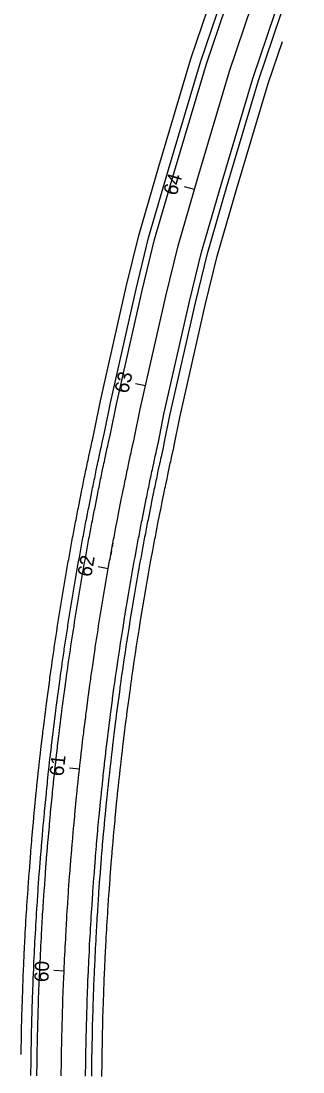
# Model space of a CAD drawing. Extents: x 2318076 to 2324211, y 613525 to 629939.
# Drawn here: x 2318594 to 2318733, y 620852 to 621371 of the extents above; entities that cross this region are included whole.
import ezdxf

# ---------------------------------------------------------------- set-up
doc = ezdxf.new("R2010")
doc.units = 0
for name, color, linetype in [('GE_P_CL_50', 7, 'Continuous'), ('PV_P_EOP', 7, 'Continuous'), ('PV_P_Shoulder', 7, 'Continuous'), ('RD_X_GR_Lt', 7, 'Continuous'), ('RD_X_GR_Rt', 7, 'Continuous')]:
    doc.layers.add(name, color=color, linetype=linetype)

msp = doc.modelspace()

# ---------------------------------------------------------------- linework, layer by layer
at = {"layer": 'GE_P_CL_50'}
for p, q in [((2318679.71, 621288.18), (2318674.91, 621289.57)), ((2318655.58, 621191.17), (2318650.7, 621192.27)), ((2318637.23, 621100.93), (2318632.3, 621101.8)), ((2318623.06, 621001.95), (2318618.09, 621002.5)), ((2318615.45, 620902.26), (2318610.45, 620902.47))]:
    msp.add_line(p, q, dxfattribs=at)
msp.add_lwpolyline([(2318614.1, 620850.47), (2318614.18, 620857.38), (2318614.19, 620858.37), (2318614.43, 620871.21), (2318614.45, 620872.19), (2318614.52, 620875.16), (2318614.55, 620876.14), (2318614.63, 620879.11), (2318614.65, 620880.09), (2318614.74, 620883.06), (2318614.77, 620884.04), (2318614.87, 620887), (2318614.9, 620887.99), (2318615.04, 620891.94), (2318615.07, 620892.93), (2318615.15, 620894.9), (2318615.19, 620895.89), (2318615.22, 620896.87), (2318615.26, 620897.86), (2318615.47, 620902.8), (2318615.51, 620903.78), (2318615.56, 620904.77), (2318615.6, 620905.76), (2318615.74, 620908.72), (2318615.79, 620909.7), (2318615.93, 620912.66), (2318615.98, 620913.65), (2318616.03, 620914.64), (2318616.08, 620915.62), (2318616.24, 620918.58), (2318616.29, 620919.57), (2318616.46, 620922.53), (2318616.51, 620923.51), (2318616.57, 620924.5), (2318616.63, 620925.48), (2318616.8, 620928.44), (2318616.86, 620929.43), (2318617.05, 620932.39), (2318617.11, 620933.37), (2318617.64, 620941.26), (2318617.7, 620942.24), (2318618.2, 620949.14), (2318618.27, 620950.12), (2318618.96, 620958.99), (2318619.04, 620959.97), (2318619.45, 620964.89), (2318619.54, 620965.88), (2318620.14, 620972.76), (2318620.23, 620973.75), (2318620.68, 620978.66), (2318620.78, 620979.65), (2318621.64, 620988.5), (2318621.74, 620989.48), (2318622.14, 620993.41), (2318622.25, 620994.39), (2318622.77, 620999.3), (2318622.87, 621000.28), (2318623.41, 621005.19), (2318623.52, 621006.17), (2318624.08, 621011.08), (2318624.2, 621012.06), (2318624.78, 621016.97), (2318624.9, 621017.95), (2318625.13, 621019.91), (2318625.25, 621020.89), (2318626.11, 621027.75), (2318626.23, 621028.73), (2318626.48, 621030.69), (2318626.61, 621031.67), (2318627.39, 621037.54), (2318627.52, 621038.52), (2318628.18, 621043.42), (2318628.32, 621044.4), (2318628.59, 621046.35), (2318628.73, 621047.33), (2318629, 621049.29), (2318629.14, 621050.26), (2318629.42, 621052.22), (2318629.56, 621053.2), (2318630.27, 621058.08), (2318630.42, 621059.06), (2318630.71, 621061.02), (2318630.86, 621061.99), (2318631.45, 621065.9), (2318631.6, 621066.87), (2318632.05, 621069.8), (2318632.2, 621070.78), (2318632.51, 621072.73), (2318632.66, 621073.71), (2318633.44, 621078.58), (2318633.6, 621079.56), (2318634.4, 621084.43), (2318634.56, 621085.41), (2318635.38, 621090.28), (2318635.55, 621091.25), (2318636.38, 621096.12), (2318636.55, 621097.09), (2318636.72, 621098.06), (2318636.89, 621099.04), (2318637.24, 621100.98), (2318637.41, 621101.95), (2318637.76, 621103.9), (2318637.93, 621104.87), (2318638.11, 621105.84), (2318638.28, 621106.81), (2318638.64, 621108.76), (2318638.81, 621109.73), (2318638.64, 621108.76), (2318638.46, 621107.79), (2318638.99, 621110.7), (2318639.17, 621111.67), (2318639.35, 621112.64), (2318639.53, 621113.61), (2318639.35, 621112.64), (2318639.17, 621111.67), (2318639.53, 621113.61), (2318639.71, 621114.59), (2318639.89, 621115.56), (2318640.08, 621116.53), (2318640.26, 621117.5), (2318640.44, 621118.47), (2318640.63, 621119.44), (2318640.81, 621120.41), (2318641, 621121.38), (2318641.18, 621122.35), (2318641.74, 621125.26), (2318641.93, 621126.23), (2318642.12, 621127.2), (2318642.31, 621128.17), (2318643.66, 621134.95), (2318643.85, 621135.92), (2318644.24, 621137.85), (2318644.44, 621138.82), (2318645.03, 621141.72), (2318645.23, 621142.69), (2318645.43, 621143.66), (2318645.63, 621144.63), (2318645.83, 621145.59), (2318646.03, 621146.56), (2318646.64, 621149.46), (2318646.85, 621150.43), (2318647.05, 621151.39), (2318647.26, 621152.36), (2318648.29, 621157.19), (2318648.5, 621158.15), (2318648.71, 621159.12), (2318648.92, 621160.08), (2318649.99, 621164.91), (2318650.2, 621165.87), (2318652.99, 621179.7), (2318665.59, 621235.58), (2318671.65, 621260.37), (2318681.36, 621293.88), (2318697.08, 621346.57), (2318719.13, 621411.93)], dxfattribs=at)
at = {"layer": 'PV_P_EOP'}
for points in [[(2318602.1, 620850.59), (2318602.18, 620857.53), (2318602.19, 620858.56), (2318602.43, 620871.45), (2318602.45, 620872.48), (2318602.52, 620875.46), (2318602.55, 620876.46), (2318602.63, 620879.44), (2318602.66, 620880.44), (2318602.75, 620883.42), (2318602.78, 620884.42), (2318602.87, 620887.4), (2318602.91, 620888.4), (2318603.04, 620892.37), (2318603.08, 620893.37), (2318603.16, 620895.36), (2318603.19, 620896.36), (2318603.23, 620897.35), (2318603.27, 620898.35), (2318603.48, 620903.31), (2318603.53, 620904.31), (2318603.57, 620905.31), (2318603.62, 620906.31), (2318603.75, 620909.28), (2318603.8, 620910.28), (2318603.95, 620913.26), (2318604, 620914.26), (2318604.05, 620915.25), (2318604.1, 620916.25), (2318604.26, 620919.22), (2318604.31, 620920.23), (2318604.48, 620923.2), (2318604.53, 620924.2), (2318604.59, 620925.19), (2318604.65, 620926.19), (2318604.83, 620929.16), (2318604.89, 620930.16), (2318605.07, 620933.14), (2318605.14, 620934.15), (2318605.66, 620942.07), (2318605.73, 620943.09), (2318606.23, 620950.01), (2318606.31, 620951.03), (2318607, 620959.94), (2318607.08, 620960.95), (2318607.5, 620965.9), (2318607.58, 620966.91), (2318608.19, 620973.83), (2318608.28, 620974.84), (2318608.74, 620979.78), (2318608.83, 620980.79), (2318609.7, 620989.68), (2318609.8, 620990.69), (2318610.21, 620994.64), (2318610.31, 620995.65), (2318610.84, 621000.58), (2318610.94, 621001.59), (2318611.49, 621006.52), (2318611.6, 621007.52), (2318612.16, 621012.45), (2318612.28, 621013.46), (2318612.86, 621018.39), (2318612.98, 621019.38), (2318613.22, 621021.36), (2318613.34, 621022.36), (2318614.2, 621029.25), (2318614.33, 621030.25), (2318614.58, 621032.22), (2318614.71, 621033.22), (2318615.49, 621039.12), (2318615.62, 621040.13), (2318616.29, 621045.05), (2318616.43, 621046.04), (2318616.7, 621048.01), (2318616.84, 621049), (2318617.12, 621050.97), (2318617.26, 621051.96), (2318617.54, 621053.92), (2318617.68, 621054.92), (2318618.4, 621059.83), (2318618.55, 621060.82), (2318618.84, 621062.79), (2318618.99, 621063.78), (2318619.59, 621067.71), (2318619.74, 621068.7), (2318620.19, 621071.64), (2318620.35, 621072.63), (2318620.66, 621074.6), (2318620.81, 621075.59), (2318621.6, 621080.49), (2318621.76, 621081.49), (2318622.56, 621086.38), (2318622.73, 621087.38), (2318623.55, 621092.28), (2318623.72, 621093.27), (2318624.56, 621098.16), (2318624.73, 621099.15), (2318624.9, 621100.13), (2318625.08, 621101.11), (2318625.42, 621103.07), (2318625.6, 621104.06), (2318625.95, 621106.01), (2318626.12, 621106.99), (2318626.3, 621107.97), (2318626.48, 621108.96), (2318626.83, 621110.91), (2318627.19, 621112.87), (2318627.37, 621113.85), (2318627.55, 621114.83), (2318627.73, 621115.81), (2318627.92, 621116.79), (2318628.1, 621117.76), (2318628.28, 621118.74), (2318628.47, 621119.72), (2318628.65, 621120.7), (2318628.84, 621121.68), (2318629.02, 621122.66), (2318629.21, 621123.63), (2318629.4, 621124.62), (2318629.96, 621127.54), (2318630.15, 621128.52), (2318630.34, 621129.5), (2318630.54, 621130.49), (2318631.89, 621137.3), (2318632.09, 621138.29), (2318632.48, 621140.24), (2318632.68, 621141.22), (2318633.28, 621144.14), (2318633.48, 621145.12), (2318633.68, 621146.09), (2318633.88, 621147.07), (2318634.08, 621148.04), (2318634.29, 621149.02), (2318634.9, 621151.93), (2318635.11, 621152.91), (2318635.31, 621153.89), (2318635.52, 621154.87), (2318636.56, 621159.72), (2318636.78, 621160.7), (2318636.99, 621161.67), (2318637.2, 621162.65), (2318638.27, 621167.5), (2318638.46, 621168.36), (2318641.25, 621182.21), (2318653.91, 621238.32), (2318660.05, 621263.47), (2318669.85, 621297.27), (2318685.64, 621350.2), (2318707.83, 621415.98)], [(2318650.44, 621106.61), (2318651.33, 621111.42), (2318651.51, 621112.38), (2318651.69, 621113.35), (2318651.87, 621114.31), (2318652.05, 621115.27), (2318652.23, 621116.24), (2318652.41, 621117.2), (2318652.6, 621118.16), (2318652.78, 621119.12), (2318652.97, 621120.08), (2318653.52, 621122.98), (2318653.71, 621123.94), (2318653.9, 621124.9), (2318654.08, 621125.85), (2318655.42, 621132.6), (2318655.61, 621133.55), (2318656, 621135.47), (2318656.2, 621136.42), (2318656.79, 621139.31), (2318656.98, 621140.27), (2318657.18, 621141.23), (2318657.38, 621142.19), (2318657.58, 621143.15), (2318657.78, 621144.1), (2318658.39, 621146.99), (2318658.59, 621147.94), (2318658.79, 621148.9), (2318658.99, 621149.85), (2318660.02, 621154.66), (2318660.23, 621155.61), (2318660.44, 621156.56), (2318660.65, 621157.51), (2318661.7, 621162.31), (2318661.94, 621163.38), (2318664.73, 621177.19), (2318677.27, 621232.84), (2318683.25, 621257.27), (2318692.87, 621290.49), (2318708.52, 621342.94), (2318730.43, 621407.88)], [(2318626.1, 620850.35), (2318626.18, 620857.23), (2318626.19, 620858.18), (2318626.42, 620870.96), (2318626.45, 620871.91), (2318626.52, 620874.86), (2318626.54, 620875.83), (2318626.62, 620878.78), (2318626.65, 620879.75), (2318626.74, 620882.69), (2318626.77, 620883.67), (2318626.86, 620886.61), (2318626.89, 620887.58), (2318627.03, 620891.51), (2318627.07, 620892.48), (2318627.14, 620894.44), (2318627.18, 620895.42), (2318627.22, 620896.4), (2318627.25, 620897.37), (2318627.46, 620902.28), (2318627.5, 620903.25), (2318627.55, 620904.23), (2318627.59, 620905.21), (2318627.73, 620908.15), (2318627.77, 620909.12), (2318627.92, 620912.07), (2318627.97, 620913.04), (2318628.02, 620914.02), (2318628.07, 620914.99), (2318628.22, 620917.94), (2318628.28, 620918.91), (2318628.44, 620921.85), (2318628.49, 620922.83), (2318628.55, 620923.8), (2318628.61, 620924.78), (2318628.78, 620927.72), (2318628.84, 620928.69), (2318629.03, 620931.63), (2318629.09, 620932.59), (2318629.61, 620940.44), (2318629.67, 620941.39), (2318630.17, 620948.26), (2318630.24, 620949.21), (2318630.93, 620958.03), (2318631, 620958.99), (2318631.41, 620963.88), (2318631.49, 620964.84), (2318632.09, 620971.7), (2318632.18, 620972.65), (2318632.63, 620977.55), (2318632.72, 620978.5), (2318633.58, 620987.31), (2318633.68, 620988.26), (2318634.08, 620992.17), (2318634.18, 620993.14), (2318634.7, 620998.02), (2318634.8, 620998.98), (2318635.34, 621003.87), (2318635.45, 621004.83), (2318636.01, 621009.71), (2318636.12, 621010.67), (2318636.69, 621015.55), (2318636.81, 621016.51), (2318637.05, 621018.46), (2318637.16, 621019.42), (2318638.01, 621026.25), (2318638.14, 621027.21), (2318638.39, 621029.16), (2318638.51, 621030.12), (2318639.28, 621035.96), (2318639.41, 621036.92), (2318640.07, 621041.79), (2318640.2, 621042.75), (2318640.47, 621044.69), (2318640.61, 621045.66), (2318640.88, 621047.61), (2318641.02, 621048.57), (2318641.3, 621050.52), (2318641.44, 621051.48), (2318642.15, 621056.34), (2318642.29, 621057.3), (2318642.58, 621059.24), (2318642.72, 621060.2), (2318643.31, 621064.09), (2318643.46, 621065.05), (2318643.91, 621067.96), (2318644.06, 621068.92), (2318644.36, 621070.86), (2318644.52, 621071.82), (2318645.29, 621076.67), (2318645.45, 621077.63), (2318646.24, 621082.48), (2318646.4, 621083.43), (2318647.21, 621088.28), (2318647.38, 621089.23), (2318648.21, 621094.07), (2318648.38, 621095.03), (2318648.54, 621095.99), (2318648.71, 621096.96), (2318649.05, 621098.89), (2318649.23, 621099.85), (2318649.57, 621101.78), (2318649.74, 621102.75), (2318649.92, 621103.71), (2318650.09, 621104.67), (2318650.44, 621106.61)]]:
    msp.add_lwpolyline(points, dxfattribs=at)
at = {"layer": 'PV_P_Shoulder'}
for points in [[(2318599.1, 620850.62), (2318599.18, 620857.57), (2318599.19, 620858.61), (2318599.43, 620871.52), (2318599.45, 620872.55), (2318599.53, 620875.53), (2318599.55, 620876.54), (2318599.63, 620879.52), (2318599.66, 620880.53), (2318599.75, 620883.51), (2318599.78, 620884.51), (2318599.87, 620887.5), (2318599.91, 620888.5), (2318600.05, 620892.48), (2318600.08, 620893.48), (2318600.16, 620895.47), (2318600.2, 620896.47), (2318600.24, 620897.47), (2318600.28, 620898.48), (2318600.48, 620903.44), (2318600.53, 620904.45), (2318600.57, 620905.44), (2318600.62, 620906.44), (2318600.76, 620909.42), (2318600.8, 620910.43), (2318600.95, 620913.41), (2318601, 620914.41), (2318601.05, 620915.41), (2318601.1, 620916.41), (2318601.26, 620919.38), (2318601.32, 620920.39), (2318601.48, 620923.37), (2318601.54, 620924.37), (2318601.6, 620925.37), (2318601.65, 620926.37), (2318601.83, 620929.34), (2318601.89, 620930.35), (2318602.08, 620933.33), (2318602.14, 620934.34), (2318602.67, 620942.27), (2318602.74, 620943.3), (2318603.24, 620950.23), (2318603.32, 620951.26), (2318604.01, 620960.17), (2318604.09, 620961.2), (2318604.51, 620966.15), (2318604.59, 620967.17), (2318605.2, 620974.09), (2318605.29, 620975.11), (2318605.75, 620980.06), (2318605.85, 620981.08), (2318606.71, 620989.98), (2318606.82, 620991), (2318607.22, 620994.95), (2318607.33, 620995.96), (2318607.85, 621000.9), (2318607.96, 621001.91), (2318608.51, 621006.85), (2318608.62, 621007.86), (2318609.18, 621012.8), (2318609.3, 621013.81), (2318609.88, 621018.74), (2318610, 621019.74), (2318610.24, 621021.72), (2318610.37, 621022.73), (2318611.23, 621029.63), (2318611.35, 621030.63), (2318611.61, 621032.61), (2318611.74, 621033.61), (2318612.52, 621039.52), (2318612.65, 621040.53), (2318613.32, 621045.45), (2318613.46, 621046.45), (2318613.73, 621048.42), (2318613.87, 621049.42), (2318614.15, 621051.39), (2318614.29, 621052.38), (2318614.57, 621054.35), (2318614.72, 621055.35), (2318615.43, 621060.27), (2318615.58, 621061.26), (2318615.87, 621063.23), (2318616.02, 621064.23), (2318616.62, 621068.16), (2318616.77, 621069.16), (2318617.23, 621072.1), (2318617.38, 621073.1), (2318617.69, 621075.06), (2318617.85, 621076.06), (2318618.63, 621080.97), (2318618.8, 621081.97), (2318619.6, 621086.87), (2318619.77, 621087.88), (2318620.59, 621092.78), (2318620.76, 621093.78), (2318621.6, 621098.67), (2318621.78, 621099.67), (2318621.95, 621100.65), (2318622.12, 621101.63), (2318622.47, 621103.59), (2318622.64, 621104.58), (2318622.99, 621106.54), (2318623.17, 621107.52), (2318623.35, 621108.51), (2318623.52, 621109.49), (2318623.88, 621111.45), (2318624.24, 621113.41), (2318624.42, 621114.39), (2318624.6, 621115.37), (2318624.78, 621116.36), (2318624.97, 621117.34), (2318625.15, 621118.32), (2318625.33, 621119.3), (2318625.52, 621120.28), (2318625.7, 621121.26), (2318625.89, 621122.24), (2318626.08, 621123.22), (2318626.26, 621124.2), (2318626.45, 621125.18), (2318627.02, 621128.11), (2318627.21, 621129.09), (2318627.4, 621130.07), (2318627.59, 621131.07), (2318628.95, 621137.89), (2318629.15, 621138.88), (2318629.54, 621140.83), (2318629.74, 621141.82), (2318630.34, 621144.74), (2318630.54, 621145.72), (2318630.74, 621146.7), (2318630.94, 621147.67), (2318631.15, 621148.65), (2318631.35, 621149.63), (2318631.96, 621152.55), (2318632.17, 621153.53), (2318632.38, 621154.51), (2318632.59, 621155.49), (2318633.63, 621160.35), (2318633.84, 621161.34), (2318634.06, 621162.31), (2318634.27, 621163.29), (2318635.34, 621168.15), (2318635.53, 621168.98), (2318638.32, 621182.83), (2318650.99, 621239.01), (2318657.15, 621264.24), (2318666.97, 621298.11), (2318682.78, 621351.11), (2318705.01, 621416.99)], [(2318653.39, 621106.06), (2318654.28, 621110.88), (2318654.46, 621111.83), (2318654.64, 621112.8), (2318654.82, 621113.76), (2318655, 621114.72), (2318655.18, 621115.68), (2318655.36, 621116.64), (2318655.54, 621117.6), (2318655.73, 621118.56), (2318655.91, 621119.52), (2318656.47, 621122.41), (2318656.65, 621123.36), (2318656.84, 621124.32), (2318657.03, 621125.27), (2318658.36, 621132.01), (2318658.55, 621132.95), (2318658.94, 621134.87), (2318659.14, 621135.83), (2318659.73, 621138.71), (2318659.92, 621139.66), (2318660.12, 621140.62), (2318660.32, 621141.58), (2318660.52, 621142.54), (2318660.72, 621143.49), (2318661.32, 621146.37), (2318661.52, 621147.32), (2318661.72, 621148.28), (2318661.93, 621149.22), (2318662.96, 621154.02), (2318663.16, 621154.97), (2318663.37, 621155.93), (2318663.58, 621156.87), (2318664.63, 621161.67), (2318664.87, 621162.76), (2318667.66, 621176.57), (2318680.19, 621232.15), (2318686.15, 621256.5), (2318695.75, 621289.65), (2318711.38, 621342.03), (2318733.25, 621406.87)], [(2318629.1, 620850.32), (2318629.18, 620857.19), (2318629.19, 620858.13), (2318629.42, 620870.9), (2318629.44, 620871.84), (2318629.52, 620874.78), (2318629.54, 620875.75), (2318629.62, 620878.69), (2318629.65, 620879.66), (2318629.73, 620882.6), (2318629.76, 620883.57), (2318629.86, 620886.51), (2318629.89, 620887.48), (2318630.03, 620891.4), (2318630.06, 620892.37), (2318630.14, 620894.33), (2318630.17, 620895.3), (2318630.21, 620896.28), (2318630.25, 620897.25), (2318630.46, 620902.15), (2318630.5, 620903.12), (2318630.54, 620904.1), (2318630.59, 620905.07), (2318630.72, 620908.01), (2318630.77, 620908.98), (2318630.91, 620911.92), (2318630.96, 620912.89), (2318631.01, 620913.87), (2318631.06, 620914.84), (2318631.22, 620917.78), (2318631.27, 620918.74), (2318631.43, 620921.68), (2318631.49, 620922.65), (2318631.55, 620923.63), (2318631.6, 620924.6), (2318631.78, 620927.54), (2318631.84, 620928.51), (2318632.02, 620931.45), (2318632.08, 620932.4), (2318632.6, 620940.24), (2318632.67, 620941.18), (2318633.16, 620948.04), (2318633.23, 620948.98), (2318633.92, 620957.8), (2318633.99, 620958.74), (2318634.4, 620963.63), (2318634.48, 620964.58), (2318635.08, 620971.43), (2318635.17, 620972.38), (2318635.62, 620977.27), (2318635.71, 620978.21), (2318636.57, 620987.01), (2318636.66, 620987.96), (2318637.06, 620991.87), (2318637.16, 620992.82), (2318637.68, 620997.7), (2318637.79, 620998.66), (2318638.32, 621003.54), (2318638.43, 621004.49), (2318638.99, 621009.37), (2318639.1, 621010.32), (2318639.67, 621015.19), (2318639.79, 621016.15), (2318640.02, 621018.1), (2318640.14, 621019.05), (2318640.99, 621025.87), (2318641.11, 621026.83), (2318641.36, 621028.77), (2318641.49, 621029.73), (2318642.25, 621035.57), (2318642.38, 621036.52), (2318643.04, 621041.38), (2318643.17, 621042.34), (2318643.44, 621044.28), (2318643.58, 621045.24), (2318643.85, 621047.18), (2318643.99, 621048.15), (2318644.27, 621050.09), (2318644.41, 621051.05), (2318645.11, 621055.9), (2318645.26, 621056.86), (2318645.54, 621058.8), (2318645.69, 621059.75), (2318646.28, 621063.64), (2318646.42, 621064.59), (2318646.87, 621067.5), (2318647.02, 621068.46), (2318647.33, 621070.4), (2318647.48, 621071.35), (2318648.25, 621076.2), (2318648.41, 621077.14), (2318649.2, 621081.99), (2318649.36, 621082.93), (2318650.17, 621087.78), (2318650.33, 621088.72), (2318651.17, 621093.56), (2318651.33, 621094.51), (2318651.5, 621095.48), (2318651.67, 621096.44), (2318652.01, 621098.37), (2318652.18, 621099.33), (2318652.52, 621101.26), (2318652.7, 621102.22), (2318652.87, 621103.18), (2318653.04, 621104.14), (2318653.39, 621106.07)]]:
    msp.add_lwpolyline(points, dxfattribs=at)
at = {"layer": 'RD_X_GR_Lt'}
msp.add_lwpolyline([(2318594.23, 620860.98), (2318594.43, 620871.62), (2318594.45, 620872.67), (2318594.53, 620875.65), (2318594.55, 620876.67), (2318594.63, 620879.66), (2318594.66, 620880.67), (2318594.75, 620883.66), (2318594.78, 620884.67), (2318594.88, 620887.66), (2318594.91, 620888.68), (2318595.05, 620892.66), (2318595.09, 620893.67), (2318595.16, 620895.66), (2318595.2, 620896.67), (2318595.24, 620897.67), (2318595.28, 620898.68), (2318595.49, 620903.65), (2318595.53, 620904.67), (2318595.58, 620905.67), (2318595.62, 620906.67), (2318595.76, 620909.66), (2318595.81, 620910.67), (2318595.96, 620913.66), (2318596.01, 620914.66), (2318596.06, 620915.66), (2318596.11, 620916.67), (2318596.27, 620919.65), (2318596.32, 620920.67), (2318596.49, 620923.65), (2318596.55, 620924.66), (2318596.6, 620925.65), (2318596.66, 620926.66), (2318596.84, 620929.64), (2318596.9, 620930.66), (2318597.09, 620933.64), (2318597.15, 620934.67), (2318597.68, 620942.61), (2318597.75, 620943.65), (2318598.25, 620950.6), (2318598.33, 620951.64), (2318599.03, 620960.57), (2318599.11, 620961.61), (2318599.52, 620966.57), (2318599.61, 620967.6), (2318600.22, 620974.54), (2318600.31, 620975.57), (2318600.77, 620980.52), (2318600.87, 620981.56), (2318601.74, 620990.47), (2318601.84, 620991.5), (2318602.25, 620995.47), (2318602.36, 620996.48), (2318602.88, 621001.43), (2318602.99, 621002.45), (2318603.54, 621007.4), (2318603.65, 621008.42), (2318604.22, 621013.37), (2318604.33, 621014.39), (2318604.92, 621019.33), (2318605.04, 621020.34), (2318605.28, 621022.32), (2318605.4, 621023.34), (2318606.27, 621030.25), (2318606.39, 621031.27), (2318606.65, 621033.25), (2318606.78, 621034.26), (2318607.56, 621040.18), (2318607.7, 621041.2), (2318608.37, 621046.13), (2318608.51, 621047.14), (2318608.78, 621049.11), (2318608.92, 621050.11), (2318609.2, 621052.09), (2318609.34, 621053.09), (2318609.62, 621055.06), (2318609.77, 621056.07), (2318610.49, 621060.99), (2318610.64, 621062), (2318610.93, 621063.97), (2318611.08, 621064.97), (2318611.68, 621068.91), (2318611.83, 621069.92), (2318612.29, 621072.87), (2318612.44, 621073.87), (2318612.75, 621075.84), (2318612.91, 621076.85), (2318613.7, 621081.76), (2318613.86, 621082.78), (2318614.67, 621087.69), (2318614.84, 621088.7), (2318615.66, 621093.61), (2318615.83, 621094.62), (2318616.68, 621099.53), (2318616.85, 621100.53), (2318617.02, 621101.51), (2318617.2, 621102.5), (2318617.54, 621104.47), (2318617.72, 621105.46), (2318618.07, 621107.42), (2318618.25, 621108.41), (2318618.43, 621109.39), (2318618.6, 621110.38), (2318618.96, 621112.35), (2318619.32, 621114.31), (2318619.5, 621115.3), (2318619.69, 621116.29), (2318619.87, 621117.27), (2318620.05, 621118.25), (2318620.24, 621119.24), (2318620.42, 621120.22), (2318620.6, 621121.2), (2318620.79, 621122.19), (2318620.98, 621123.17), (2318621.16, 621124.15), (2318621.35, 621125.14), (2318621.54, 621126.13), (2318622.11, 621129.06), (2318622.3, 621130.05), (2318622.49, 621131.03), (2318622.69, 621132.03), (2318624.04, 621138.87), (2318624.24, 621139.87), (2318624.64, 621141.83), (2318624.84, 621142.82), (2318625.44, 621145.74), (2318625.64, 621146.73), (2318625.85, 621147.71), (2318626.05, 621148.69), (2318626.25, 621149.67), (2318626.46, 621150.66), (2318627.07, 621153.58), (2318627.28, 621154.57), (2318627.49, 621155.55), (2318627.7, 621156.54), (2318628.74, 621161.41), (2318628.96, 621162.4), (2318629.17, 621163.37), (2318629.39, 621164.36), (2318630.46, 621169.23), (2318630.63, 621170.02), (2318633.43, 621183.88), (2318646.12, 621240.15), (2318652.32, 621265.53), (2318662.17, 621299.52), (2318678.02, 621352.63), (2318700.3, 621418.68)], dxfattribs=at)
at = {"layer": 'RD_X_GR_Rt'}
for points in [[(2318658.31, 621105.16), (2318659.2, 621109.97), (2318659.37, 621110.92), (2318659.55, 621111.88), (2318659.73, 621112.83), (2318659.91, 621113.79), (2318660.09, 621114.75), (2318660.27, 621115.71), (2318660.46, 621116.66), (2318660.64, 621117.62), (2318660.82, 621118.57), (2318661.38, 621121.46), (2318661.56, 621122.41), (2318661.75, 621123.36), (2318661.93, 621124.3), (2318663.27, 621131.03), (2318663.46, 621131.96), (2318663.84, 621133.88), (2318664.04, 621134.83), (2318664.62, 621137.7), (2318664.82, 621138.65), (2318665.02, 621139.61), (2318665.21, 621140.56), (2318665.41, 621141.52), (2318665.61, 621142.46), (2318666.21, 621145.34), (2318666.41, 621146.29), (2318666.62, 621147.24), (2318666.82, 621148.18), (2318667.84, 621152.97), (2318668.05, 621153.91), (2318668.26, 621154.86), (2318668.46, 621155.8), (2318669.51, 621160.59), (2318669.77, 621161.72), (2318672.55, 621175.52), (2318685.06, 621231.01), (2318690.98, 621255.21), (2318700.55, 621288.24), (2318716.14, 621340.51), (2318723.13, 621361.23)], [(2318634.1, 620850.27), (2318634.18, 620857.13), (2318634.19, 620858.05), (2318634.42, 620870.79), (2318634.44, 620871.72), (2318634.51, 620874.66), (2318634.54, 620875.62), (2318634.62, 620878.56), (2318634.64, 620879.52), (2318634.73, 620882.45), (2318634.76, 620883.41), (2318634.86, 620886.35), (2318634.89, 620887.31), (2318635.02, 620891.22), (2318635.06, 620892.18), (2318635.13, 620894.14), (2318635.17, 620895.11), (2318635.21, 620896.08), (2318635.25, 620897.04), (2318635.45, 620901.94), (2318635.49, 620902.9), (2318635.54, 620903.87), (2318635.58, 620904.84), (2318635.72, 620907.78), (2318635.76, 620908.74), (2318635.91, 620911.67), (2318635.96, 620912.64), (2318636.01, 620913.61), (2318636.06, 620914.58), (2318636.21, 620917.51), (2318636.26, 620918.47), (2318636.43, 620921.4), (2318636.48, 620922.37), (2318636.54, 620923.34), (2318636.59, 620924.31), (2318636.77, 620927.24), (2318636.83, 620928.2), (2318637.01, 620931.13), (2318637.07, 620932.07), (2318637.59, 620939.9), (2318637.65, 620940.83), (2318638.15, 620947.68), (2318638.22, 620948.6), (2318638.9, 620957.4), (2318638.98, 620958.33), (2318639.38, 620963.21), (2318639.46, 620964.15), (2318640.06, 620970.99), (2318640.15, 620971.93), (2318640.6, 620976.81), (2318640.69, 620977.74), (2318641.54, 620986.52), (2318641.64, 620987.45), (2318642.04, 620991.35), (2318642.14, 620992.3), (2318642.65, 620997.17), (2318642.76, 620998.11), (2318643.29, 621002.98), (2318643.4, 621003.93), (2318643.95, 621008.79), (2318644.06, 621009.74), (2318644.64, 621014.6), (2318644.75, 621015.55), (2318644.99, 621017.49), (2318645.1, 621018.44), (2318645.95, 621025.25), (2318646.07, 621026.19), (2318646.32, 621028.13), (2318646.44, 621029.08), (2318647.21, 621034.91), (2318647.34, 621035.85), (2318648, 621040.7), (2318648.13, 621041.65), (2318648.4, 621043.59), (2318648.53, 621044.55), (2318648.8, 621046.48), (2318648.94, 621047.44), (2318649.22, 621049.38), (2318649.35, 621050.33), (2318650.06, 621055.18), (2318650.2, 621056.12), (2318650.49, 621058.06), (2318650.63, 621059.01), (2318651.22, 621062.88), (2318651.37, 621063.83), (2318651.81, 621066.73), (2318651.96, 621067.69), (2318652.27, 621069.62), (2318652.42, 621070.57), (2318653.19, 621075.4), (2318653.34, 621076.34), (2318654.13, 621081.17), (2318654.29, 621082.11), (2318655.1, 621086.94), (2318655.26, 621087.88), (2318656.09, 621092.71), (2318656.26, 621093.65), (2318656.42, 621094.61), (2318656.59, 621095.57), (2318656.93, 621097.5), (2318657.1, 621098.45), (2318657.45, 621100.37), (2318657.62, 621101.33), (2318657.79, 621102.29), (2318657.96, 621103.25), (2318658.31, 621105.17)]]:
    msp.add_lwpolyline(points, dxfattribs=at)

# ---------------------------------------------------------------- texts
at = {"layer": 'GE_P_CL_50'}
for s, rotation, p in [('64', 73.8403, (2318670.93, 621284.82)), ('63', 77.2933, (2318646.99, 621187.18)), ('62', 79.9935, (2318628.85, 621096.61)), ('61', 83.7134, (2318615.11, 620998.26)), ('60', 87.6014, (2318607.71, 620896.71))]:
    msp.add_text(s, height=7, rotation=rotation, dxfattribs=at).set_placement(p)

doc.saveas('drawing.dxf')
